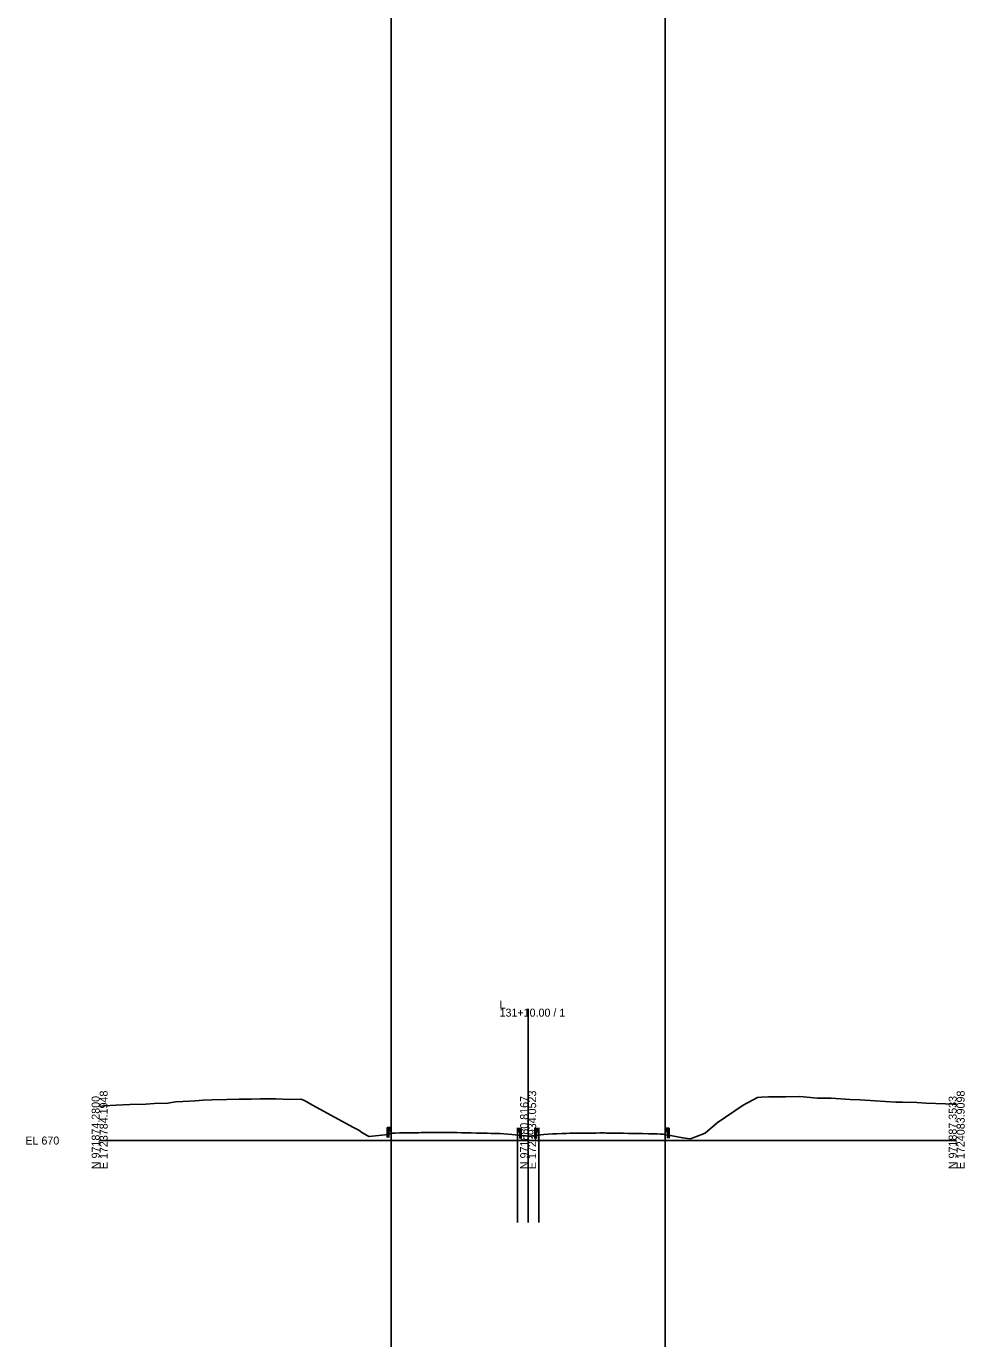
# Model space of a CAD drawing. Extents: x -26 to 303, y -29 to 15026.
# Drawn here: x -25.7 to 302.8, y 430.6 to 890 of the extents above; entities that cross this region are included whole.
import ezdxf

# ---------------------------------------------------------------- set-up
doc = ezdxf.new("R2010")
doc.units = 0
for name, color, linetype in [('Exist Cross Section Cell', 7, 'Continuous'), ('Exist XS Center Line Elevation Label', 7, 'Continuous'), ('Exist XS Ground Line', 7, 'Continuous'), ('Scratch_Level_0', 7, 'Continuous'), ('Typical Guardrail CELL', 7, 'Continuous')]:
    doc.layers.add(name, color=color, linetype=linetype)

msp = doc.modelspace()

# ---------------------------------------------------------------- linework, layer by layer
at = {"layer": 'Exist Cross Section Cell'}
for p, q in [((150, 500), (150, 546.16)), ((0, 500), (150, 500)), ((150, 500), (300, 500))]:
    msp.add_line(p, q, dxfattribs=at)
at = {"layer": 'Exist XS Ground Line'}
msp.add_lwpolyline([(0, 511.97), (1.48, 512.1), (5.82, 512.34), (10.57, 512.57), (16.21, 512.73), (19.08, 512.95), (23.84, 513.12), (26.54, 513.5), (29.09, 513.71), (33.43, 513.91), (36.22, 514.12), (39.41, 514.26), (44.51, 514.4), (48.84, 514.48), (53.08, 514.46), (56.22, 514.55), (61.7, 514.59), (66.63, 514.42), (70.38, 514.52), (71.71, 514), (74.54, 512.33), (88.9, 504.56), (90.68, 503.67), (91.77, 502.86), (93.63, 501.78), (94.28, 501.37), (97.7, 501.78), (100.96, 502.08), (101.96, 502.59), (102.24, 502.59), (102.78, 502.58), (103.4, 502.6), (104.99, 502.66), (106.69, 502.69), (107.49, 502.71), (109.11, 502.73), (110.01, 502.73), (110.81, 502.75), (111.13, 502.76), (111.58, 502.76), (112.52, 502.77), (113.92, 502.78), (115.03, 502.79), (116.22, 502.8), (117.52, 502.81), (118.84, 502.82), (120.01, 502.82), (121.1, 502.82), (122.49, 502.82), (123.11, 502.83), (124.07, 502.8), (125, 502.78), (126.67, 502.75), (127.5, 502.73), (129.29, 502.7), (130.02, 502.68), (131.94, 502.64), (132.52, 502.63), (133.07, 502.61), (135.2, 502.55), (135.66, 502.54), (137.1, 502.5), (137.56, 502.49), (140.17, 502.43), (141.44, 502.41), (144.27, 502.13), (150.19, 501.52), (155.51, 502.08), (158.55, 502.38), (159.53, 502.39), (160.06, 502.4), (161.84, 502.45), (162.54, 502.47), (163.44, 502.5), (164.58, 502.54), (165.06, 502.54), (166.61, 502.56), (167.55, 502.57), (169.06, 502.59), (170.07, 502.6), (171.17, 502.61), (172.56, 502.63), (173.87, 502.64), (175.08, 502.65), (176.72, 502.65), (177.32, 502.64), (178.2, 502.63), (180.08, 502.6), (181.62, 502.58), (182.55, 502.57), (183.42, 502.55), (185.06, 502.53), (186.84, 502.5), (187.55, 502.49), (188.15, 502.48), (189.5, 502.46), (190.06, 502.44), (192.12, 502.39), (192.58, 502.38), (193, 502.37), (195.11, 502.31), (196.35, 502.27), (197.16, 502.24), (198.03, 502.05), (199.03, 501.9), (199.78, 501.76), (204.17, 501.01), (206.63, 500.56), (207.02, 500.74), (208.38, 501.16), (211.96, 502.62), (216.16, 506.22), (225.22, 512.34), (230.27, 515.09), (231.71, 515.18), (234.15, 515.31), (240.1, 515.29), (245.08, 515.39), (251.27, 514.86), (256.05, 514.78), (262.74, 514.37), (266.13, 514.29), (271.42, 513.89), (278.76, 513.44), (281.09, 513.43), (286.08, 513.27), (289.2, 513.11), (296.08, 512.9), (298.79, 512.74), (300, 512.71)], dxfattribs=at)
at = {"layer": 'Scratch_Level_0'}
for p, q in [((102, 15009.56), (102, -28.7)), ((198, 15009.56), (198, -28.7)), ((146.28, 504.49), (146.28, 471.3)), ((153.72, 504.49), (153.72, 471.3)), ((150, 500), (150, 471.3))]:
    msp.add_line(p, q, dxfattribs=at)
at = {"layer": 'Typical Guardrail CELL'}
for p, q in [((101.18, 504.54), (100.68, 504.54)), ((100.68, 504.54), (100.68, 502.06)), ((101.18, 502.06), (100.68, 502.06)), ((100.68, 502.06), (100.68, 501.05)), ((101.18, 504.54), (101.18, 502.06)), ((101.18, 504.54), (101.68, 504.54)), ((101.18, 503.38), (101.68, 503.38)), ((101.18, 502.06), (101.18, 501.05)), ((101.68, 504.54), (101.68, 503.38)), ((101.68, 504.54), (101.97, 504.34)), ((101.68, 504.01), (101.97, 504.21)), ((101.68, 503.96), (101.68, 504.01)), ((101.68, 503.96), (101.68, 503.92)), ((101.68, 503.92), (101.97, 503.71)), ((101.68, 503.38), (101.97, 503.59)), ((146.6, 504.27), (146.31, 504.07)), ((146.6, 503.74), (146.31, 503.94)), ((146.6, 503.65), (146.31, 503.44)), ((146.6, 503.11), (146.31, 503.32)), ((147.1, 504.27), (146.6, 504.27)), ((146.6, 504.27), (146.6, 503.11)), ((146.6, 503.69), (146.6, 503.74)), ((146.6, 503.69), (146.6, 503.65)), ((147.1, 503.11), (146.6, 503.11)), ((147.1, 504.27), (147.1, 501.79)), ((147.1, 504.27), (147.6, 504.27)), ((147.1, 501.79), (147.6, 501.79)), ((147.1, 501.79), (147.1, 500.78)), ((147.6, 504.27), (147.6, 501.79)), ((147.6, 501.79), (147.6, 500.78)), ((152.9, 504.24), (152.4, 504.24)), ((152.4, 504.24), (152.4, 501.76)), ((152.9, 501.76), (152.4, 501.76)), ((152.4, 501.76), (152.4, 500.75)), ((152.9, 504.24), (152.9, 501.76)), ((152.9, 504.24), (153.4, 504.24)), ((152.9, 503.08), (153.4, 503.08)), ((152.9, 501.76), (152.9, 500.75)), ((153.4, 504.24), (153.4, 503.08)), ((153.4, 504.24), (153.69, 504.04)), ((153.4, 503.71), (153.69, 503.91)), ((153.4, 503.66), (153.4, 503.71)), ((153.4, 503.66), (153.4, 503.62)), ((153.4, 503.62), (153.69, 503.41)), ((153.4, 503.08), (153.69, 503.29)), ((198.32, 504.33), (198.03, 504.13)), ((198.32, 503.8), (198.03, 504)), ((198.32, 503.7), (198.03, 503.5)), ((198.32, 503.17), (198.03, 503.37)), ((198.82, 504.33), (198.32, 504.33)), ((198.32, 504.33), (198.32, 503.17)), ((198.32, 503.75), (198.32, 503.8)), ((198.32, 503.75), (198.32, 503.7)), ((198.82, 503.17), (198.32, 503.17)), ((198.82, 504.33), (198.82, 501.85)), ((198.82, 504.33), (199.32, 504.33)), ((198.82, 501.85), (199.32, 501.85)), ((198.82, 501.85), (198.82, 500.84)), ((199.32, 504.33), (199.32, 501.85)), ((199.32, 501.85), (199.32, 500.84))]:
    msp.add_line(p, q, dxfattribs=at)
for centre, start, end in [((101.92, 504.28), 304.9888, 54.997), ((101.92, 503.65), 304.9634, 54.9941), ((146.36, 504.01), 125.003, 235.0112), ((146.36, 503.38), 125.0059, 235.0366), ((153.64, 503.98), 304.9888, 54.997), ((153.64, 503.35), 304.9634, 54.9941), ((198.08, 504.06), 125.003, 235.0112), ((198.08, 503.44), 125.0059, 235.0366)]:
    msp.add_arc(centre, 0.0776, start, end, dxfattribs=at)

# ---------------------------------------------------------------- texts
at = {"layer": 'Exist Cross Section Cell'}
for s, p in [('L', (140, 546.16)), ('131+10.00 / 1', (140, 543.36)), ('EL 670', (-26, 498.6))]:
    msp.add_text(s, height=2.8, dxfattribs=at).set_placement(p)
for s, p in [('N 971874.2800', (0, 490)), ('E 1723784.1948', (2.8, 490)), ('N 971880.8167', (150, 490)), ('E 1723934.0523', (152.8, 490)), ('N 971887.3533', (300, 490)), ('E 1724083.9098', (302.8, 490))]:
    msp.add_text(s, height=2.8, rotation=90, dxfattribs=at).set_placement(p)
at = {"layer": 'Exist XS Center Line Elevation Label'}
msp.add_text('671.54', height=0.18, dxfattribs=at).set_placement((149.64, 501.05))

doc.saveas('drawing.dxf')
